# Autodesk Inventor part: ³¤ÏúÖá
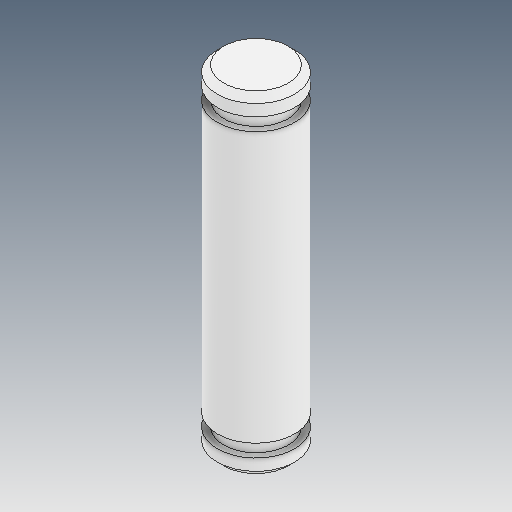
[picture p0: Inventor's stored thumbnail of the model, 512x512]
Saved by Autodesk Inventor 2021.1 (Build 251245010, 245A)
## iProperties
Created: 2021-06
Part Number: ³¤ÏúÖá
Material: Ogólny
Document SubType Name: Modeling
Designer: user
Density: 1 g/cm^3
Appearance: Domyślna
Author: user
Revision Number: ÈÎºÎ
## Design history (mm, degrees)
feature "Ðý×ª1"
node "Bryła1"
